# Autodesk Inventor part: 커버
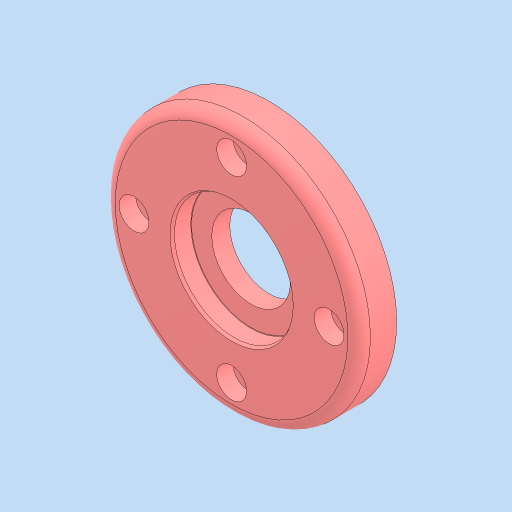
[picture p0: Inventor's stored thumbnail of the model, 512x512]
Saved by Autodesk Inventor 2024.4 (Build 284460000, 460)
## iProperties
Created: 2026-07
Part Number: 커버
Material: 알루미늄 6061
Document SubType Name: Modeling
Designer: home
Density: 2.71 g/cm^3
Appearance: 기본값
Author: jhkim
Sending System: Autodesk Inventor 2027
Preprocessor: ST-DEVELOPER v20.1
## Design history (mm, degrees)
feature "솔리드1"
node "솔리드2"
